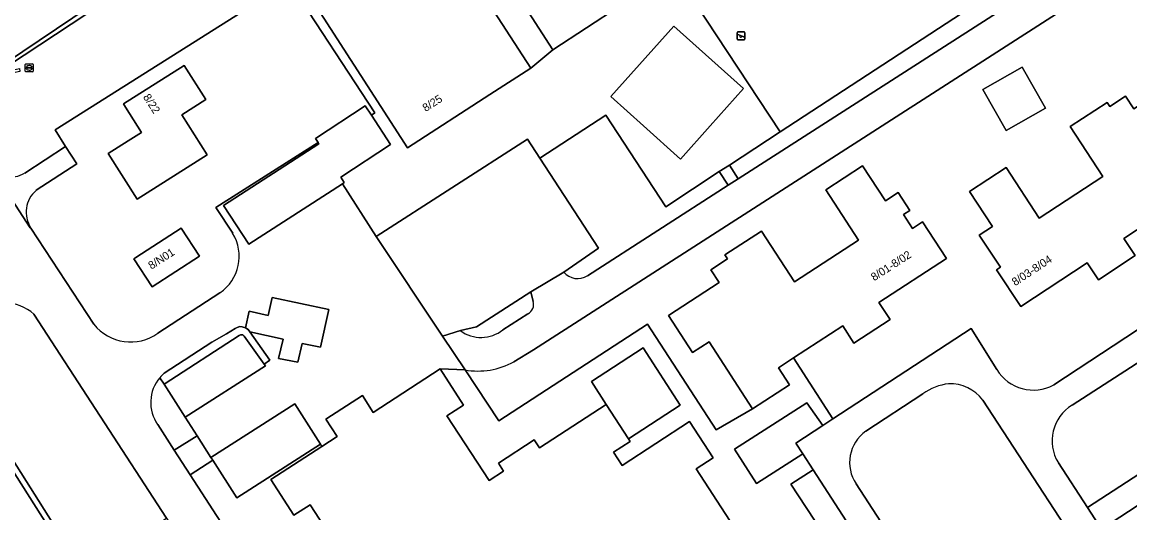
# Model space of a CAD drawing. Extents: x 159451 to 160664, y 388402 to 389723.
# Drawn here: x 159905.3 to 160043.7, y 389201.7 to 389263 of the extents above; entities that cross this region are included whole.
import ezdxf

# ---------------------------------------------------------------- set-up
doc = ezdxf.new("R2010")
doc.units = 0
for name, color, linetype in [('IMGEO_Erf', 7, 'Continuous'), ('IMGEO_Grasland_overig', 7, 'Continuous'), ('IMGEO_Groenvoorziening', 7, 'Continuous'), ('IMGEO_Haag', 7, 'Continuous'), ('IMGEO_Hek', 7, 'Continuous'), ('IMGEO_Meer_plas_ven_vijver', 7, 'Continuous'), ('IMGEO_Oever', 7, 'Continuous'), ('IMGEO_Open_loods', 7, 'Continuous'), ('IMGEO_Pand', 7, 'Continuous'), ('IMGEO_Pand_nummerreeks', 7, 'Continuous'), ('IMGEO_Parkeervlak_gesloten', 7, 'Continuous'), ('IMGEO_Parkeervlak_open', 7, 'Continuous'), ('IMGEO_Rijbaan_lokaal_gesloten', 7, 'Continuous'), ('IMGEO_Rijbaan_lokaal_open', 7, 'Continuous'), ('IMGEO_Rioolput', 7, 'Continuous'), ('IMGEO_Speelvoorziening', 7, 'Continuous'), ('IMGEO_Voetpad_gesloten', 7, 'Continuous'), ('IMGEO_Voetpad_open', 7, 'Continuous')]:
    doc.layers.add(name, color=color, linetype=linetype)

msp = doc.modelspace()

# ---------------------------------------------------------------- linework, layer by layer
at = {"layer": 'IMGEO_Erf'}
for points in [[(159942.27, 389247.93), (159941.93, 389248.42), (159948.15, 389252.52), (159948.93, 389251.33), (159949.38, 389251.62), (159938.65, 389268), (159909.42, 389249.5), (159910.72, 389247.44), (159912.11, 389245.25), (159907.06, 389241.97)], [(160041.99, 389268.82), (159969.19, 389222.03), (159966.74, 389220.55)], [(160034.2, 389217.64), (160072.99, 389243.15), (160062.76, 389252.92)], [(159931.6, 389236.59), (159929.51, 389239.79), (159942.27, 389247.93)], [(159960.64, 389219.52), (159964.87, 389213.17), (159983.45, 389225.22), (159992.01, 389212.02), (159996.56, 389214.67), (159991.13, 389223.04), (159989.07, 389221.71), (159986.07, 389226.32), (159992.41, 389230.43), (159991.37, 389232.03), (159993.45, 389233.38), (159993.11, 389233.9), (159997.69, 389236.87), (160001.8, 389230.53), (160009.8, 389235.72), (160005.72, 389242.01), (160010.32, 389244.99), (160013.16, 389240.62), (160014.77, 389241.66), (160016.22, 389239.43), (160015.44, 389238.93), (160016.56, 389237.2), (160017.81, 389238.01), (160020.79, 389233.42), (160012.36, 389227.95), (160013.75, 389225.81), (160009.22, 389222.88), (160007.84, 389225.01), (160001.7, 389221.03), (160006.59, 389213.4), (160023.88, 389224.68), (160027.09, 389219.58)], [(159906.39, 389237.24), (159914.25, 389225.23)], [(159922.25, 389224.11), (159930, 389229.16)], [(160071.89, 389220.37), (160040.16, 389199.62), (160049.04, 389185.76), (160029.31, 389172.93), (160027.27, 389171.6), (160021.26, 389180.85)]]:
    msp.add_lwpolyline(points, dxfattribs=at)
for points in [[(159928.4, 389246.38), (159919.68, 389240.85), (159916.06, 389246.57), (159918.55, 389248.15), (159920.2, 389249.19), (159918.21, 389252.32), (159917.95, 389252.74), (159925.55, 389257.56), (159928.24, 389253.3), (159925.23, 389251.39)], [(160028.25, 389249.43), (160025.34, 389254.56), (160030.26, 389257.35), (160033.17, 389252.23)], [(160051.44, 389250.36), (160056.92, 389242.01), (160052.29, 389238.96), (160050.87, 389241.12), (160042.98, 389235.94), (160044.38, 389233.81), (160039.78, 389230.79), (160038.4, 389232.89), (160030.09, 389227.43), (160027.07, 389232.03), (160027.53, 389232.34), (160024.89, 389236.34), (160026.55, 389237.42), (160023.67, 389241.8), (160028.24, 389244.79), (160032.39, 389238.47), (160040.35, 389243.69), (160036.26, 389249.91), (160040.87, 389252.94), (160041.2, 389252.44), (160043.16, 389253.73), (160044.21, 389252.13), (160050.55, 389256.29), (160053.54, 389251.73)], [(159927.45, 389233.73), (159921.54, 389229.88), (159919.25, 389233.38), (159919.52, 389233.55), (159925.17, 389237.24)]]:
    msp.add_lwpolyline(points, close=True, dxfattribs=at)
for centre, radius, start, end in [((159909.35, 389239.23), 3.56, 129.8908, 213.917), ((159926.93, 389233.71), 5.49, 303.9825, 31.7375), ((159918.84, 389228.86), 5.85, 218.3532, 305.7233), ((159962.24, 389228.59), 9.21, 259.9816, 299.2142), ((160031.66, 389222.34), 5.34, 211.2132, 298.3789)]:
    msp.add_arc(centre, radius, start, end, dxfattribs=at)
at = {"layer": 'IMGEO_Grasland_overig'}
msp.add_lwpolyline([(160001.98, 389210.39), (160005.34, 389212.58), (160003.34, 389215.4), (159994.33, 389209.63), (159997.08, 389205.34), (160002.85, 389209.04)], close=True, dxfattribs=at)
at = {"layer": 'IMGEO_Groenvoorziening'}
for points in [[(160006.58, 389324), (160004.92, 389322.82), (159998.09, 389318.4), (159982.41, 389309.54), (159903.59, 389257.53), (159904.23, 389257.01), (159904.97, 389257.18), (159905.01, 389256.78), (159904.21, 389256.61), (159903.51, 389257.12), (159903.1, 389257.75), (159896.07, 389253.11), (159898.08, 389250), (159901.3, 389245.03)], [(159995.54, 389307.61), (159964.99, 389287.63), (159973.59, 389274.49), (159977.01, 389276.73), (159979.17, 389273.42), (159980.94, 389274.58), (159987.74, 389264.19), (159989.42, 389265.29), (159986.18, 389270.18), (159974.59, 389287.89), (160008.08, 389309.69), (160019.69, 389292.19), (160033.58, 389271.21), (160000.03, 389249.27), (159993.67, 389245.11), (159994.77, 389243.39), (160043.54, 389274.71)], [(159905.61, 389244.11), (159910.72, 389247.44), (159909.42, 389249.5), (159938.65, 389268), (159939.64, 389268.65), (159954.42, 389278.21), (159953.27, 389279.96), (159964.99, 389287.63), (159995.54, 389307.61)], [(159978.23, 389251.35), (159969.99, 389245.96), (159977.33, 389234.74), (159973, 389231.74)], [(159975.92, 389231.28), (159993.51, 389242.58), (159992.41, 389244.29), (159985.72, 389239.91), (159978.23, 389251.35)], [(160077.34, 389226.4), (160076.35, 389240.87), (160068.36, 389235.7), (160036.5, 389215.12)], [(159969.16, 389228.08), (159968.86, 389229.29), (159962.06, 389224.9), (159960.05, 389224.43)], [(159917.7, 389197.36), (159923.34, 389201.02), (159906.77, 389226.48)], [(159965.37, 389224.54), (159968.5, 389226.54)], [(159933.73, 389224.28), (159933.54, 389224.59), (159933.21, 389224.77), (159932.8, 389224.9), (159932.48, 389224.94), (159932.16, 389224.82), (159931.93, 389224.69), (159930.82, 389224.04), (159929.01, 389222.99), (159923.06, 389219.11)], [(159922.5, 389218.55), (159923.02, 389217.75), (159932.41, 389223.83), (159932.49, 389223.86), (159932.59, 389223.89), (159932.66, 389223.91), (159932.8, 389223.92), (159932.88, 389223.89), (159932.96, 389223.83), (159933.04, 389223.75), (159935.55, 389220.26), (159936.23, 389220.72), (159933.73, 389224.28)], [(160034.78, 389207.9), (160038.43, 389202.32), (160059.58, 389216.09), (160069.88, 389222.95)], [(159890.55, 389218.64), (159894.92, 389221.41), (159895.56, 389221.81), (159910.27, 389198.6)], [(159895.56, 389221.81), (159894.92, 389221.41), (159909.11, 389199.03), (159909.62, 389198.21)], [(159910.27, 389198.6), (159895.56, 389221.81)], [(159925.67, 389213.61), (159923.02, 389217.75), (159922.5, 389218.55)], [(159922.23, 389212.7), (159924.29, 389209.5), (159927.16, 389211.29), (159925.67, 389213.61)], [(159945.81, 389191.21), (159947.88, 389192.55), (159941.29, 389202.68), (159939.26, 389201.36), (159936.36, 389205.82), (159942.76, 389209.97), (159942.59, 389210.24), (159932.13, 389203.53), (159929.12, 389208.23), (159926.29, 389206.42), (159942, 389182.2), (159947.2, 389185.57), (159959.65, 389166.36), (159954.45, 389162.99), (159957.06, 389158.96)], [(160013.39, 389192.75), (160004.14, 389207.04), (160001.35, 389205.26), (160008.23, 389194.81), (159996.97, 389187.41), (159993.6, 389192.53), (159982.65, 389185.33), (159987.56, 389177.52), (159991.19, 389171.98), (160000, 389177.64), (160011.84, 389185.26)]]:
    msp.add_lwpolyline(points, dxfattribs=at)
for points in [[(160019.69, 389292.19), (159986.18, 389270.18), (159989.42, 389265.29), (160000.03, 389249.27), (160033.58, 389271.21)], [(159955, 389278.59), (159968.84, 389257.2), (159971.62, 389259.5), (159968.55, 389264.2), (159957.78, 389280.5)], [(159978.29, 389215.21), (159981.08, 389210.9), (159987.54, 389215.1), (159982.88, 389222.28), (159976.42, 389218.09)]]:
    msp.add_lwpolyline(points, close=True, dxfattribs=at)
for centre, radius, start, end in [((159903.91, 389246.72), 3.11, 212.8795, 303.0689), ((159974.72, 389233.15), 2.22, 219.254, 302.7061), ((159902.79, 389221.88), 6.09, 49.1767, 123.8197), ((159967.93, 389227.69), 1.28, 296.3961, 17.2519), ((159962.64, 389227.95), 4.37, 233.6418, 308.6854), ((159926.08, 389215.55), 4.67, 130.4209, 140.0939), ((159926.19, 389215.44), 4.83, 139.8899, 214.6509), ((160039.25, 389210.65), 5.25, 121.5919, 211.583)]:
    msp.add_arc(centre, radius, start, end, dxfattribs=at)
at = {"layer": 'IMGEO_Haag'}
for points in [[(159895.56, 389221.81), (159894.92, 389221.41), (159909.11, 389199.03), (159909.62, 389198.21)], [(159910.27, 389198.6), (159895.56, 389221.81)]]:
    msp.add_lwpolyline(points, dxfattribs=at)
at = {"layer": 'IMGEO_Hek'}
for points in [[(160019.81, 389292.27), (160033.58, 389271.21), (160000.03, 389249.27)], [(160000.03, 389249.27), (159989.42, 389265.29)]]:
    msp.add_lwpolyline(points, dxfattribs=at)
at = {"layer": 'IMGEO_Meer_plas_ven_vijver'}
msp.add_lwpolyline([(159903.35, 389257.91), (159944.67, 389285.75), (160000, 389321.66), (160003.95, 389324.2), (160004.34, 389324.52), (160004.67, 389324.92), (160004.84, 389325.36), (160004.89, 389325.67), (160004.83, 389326.39), (160004.67, 389326.73), (160004.23, 389327.16), (160003.97, 389327.29), (160003.26, 389327.48), (160002.88, 389327.47), (160002.29, 389327.32), (160001.83, 389327.11), (160001.38, 389326.86), (159981.5, 389314.97), (159962.25, 389302.44), (159947.84, 389293.11), (159928.8, 389280.79), (159920.61, 389275.11), (159902.08, 389263.09)], dxfattribs=at)
at = {"layer": 'IMGEO_Oever'}
msp.add_lwpolyline([(160001.38, 389326.86), (160001.83, 389327.11), (160002.29, 389327.32), (160002.88, 389327.47), (160003.26, 389327.48), (160003.97, 389327.29), (160004.23, 389327.16), (160004.67, 389326.73), (160004.83, 389326.39), (160004.89, 389325.67), (160004.84, 389325.36), (160004.67, 389324.92), (160004.34, 389324.52), (160003.95, 389324.2), (160000, 389321.66), (159944.67, 389285.75), (159903.35, 389257.91), (159903.59, 389257.53), (159982.41, 389309.54), (159998.09, 389318.4), (160004.92, 389322.82), (160006.58, 389324), (160007.08, 389324.36)], dxfattribs=at)
at = {"layer": 'IMGEO_Open_loods'}
msp.add_lwpolyline([(159987.58, 389245.86), (159991.27, 389250), (159995.45, 389254.67), (159986.73, 389262.47), (159978.86, 389253.66), (159982.95, 389250)], close=True, dxfattribs=at)
at = {"layer": 'IMGEO_Pand'}
for points in [[(159954.42, 389278.21), (159939.64, 389268.65), (159953.46, 389247.26), (159963.74, 389253.9), (159968.84, 389257.2), (159955, 389278.59)], [(159976.93, 389269.69), (159968.55, 389264.2), (159971.62, 389259.5), (159980.01, 389264.98)], [(159925.23, 389251.39), (159928.24, 389253.3), (159925.55, 389257.56), (159917.95, 389252.74), (159918.21, 389252.32), (159920.2, 389249.19), (159918.55, 389248.15), (159916.06, 389246.57), (159919.68, 389240.85), (159928.4, 389246.38)], [(160030.26, 389257.35), (160025.34, 389254.56), (160028.25, 389249.43), (160033.17, 389252.23)], [(160030.09, 389227.43), (160038.4, 389232.89), (160039.78, 389230.79), (160044.38, 389233.81), (160042.98, 389235.94), (160050.87, 389241.12), (160052.29, 389238.96), (160056.92, 389242.01), (160051.44, 389250.36), (160053.54, 389251.73), (160050.55, 389256.29), (160044.21, 389252.13), (160043.16, 389253.73), (160041.2, 389252.44), (160040.87, 389252.94), (160036.26, 389249.91), (160040.35, 389243.69), (160032.39, 389238.47), (160028.24, 389244.79), (160023.67, 389241.8), (160026.55, 389237.42), (160024.89, 389236.34), (160027.53, 389232.34), (160027.07, 389232.03)], [(159948.15, 389252.52), (159941.93, 389248.42), (159942.27, 389247.93), (159942.38, 389247.76), (159930.47, 389240.07), (159933.62, 389235.21), (159945.31, 389242.77), (159945.54, 389242.92), (159945.11, 389243.59), (159951.31, 389247.67), (159948.93, 389251.33)], [(159996.56, 389214.67), (160001.19, 389217.67), (159999.81, 389219.8), (160001.7, 389221.03), (160007.84, 389225.01), (160009.22, 389222.88), (160013.75, 389225.81), (160012.36, 389227.95), (160020.79, 389233.42), (160017.81, 389238.01), (160016.56, 389237.2), (160015.44, 389238.93), (160016.22, 389239.43), (160014.77, 389241.66), (160013.16, 389240.62), (160010.32, 389244.99), (160005.72, 389242.01), (160009.8, 389235.72), (160001.8, 389230.53), (159997.69, 389236.87), (159993.11, 389233.9), (159993.45, 389233.38), (159991.37, 389232.03), (159992.41, 389230.43), (159986.07, 389226.32), (159989.07, 389221.71), (159991.13, 389223.04)], [(159919.25, 389233.38), (159921.54, 389229.88), (159927.45, 389233.73), (159925.17, 389237.24), (159919.52, 389233.55)]]:
    msp.add_lwpolyline(points, close=True, dxfattribs=at)
msp.add_lwpolyline([(159996.29, 389196.72), (159989.51, 389207.16), (159991.63, 389208.54), (159988.7, 389213.06), (159980.27, 389207.59), (159979.19, 389209.25), (159981.27, 389210.6), (159981.08, 389210.9), (159978.29, 389215.21), (159969.94, 389209.79), (159969.29, 389210.79), (159964.8, 389207.88), (159965.46, 389206.86), (159963.64, 389205.69), (159958.38, 389213.79), (159960.45, 389215.13), (159957.53, 389219.64), (159949.17, 389214.22), (159947.82, 389216.31), (159943.26, 389213.35), (159944.65, 389211.2), (159942.76, 389209.97), (159936.36, 389205.82), (159939.26, 389201.36), (159941.29, 389202.68), (159947.88, 389192.55)], dxfattribs=at)
at = {"layer": 'IMGEO_Parkeervlak_gesloten'}
msp.add_lwpolyline([(159935.71, 389220.04), (159935.55, 389220.26), (159933.04, 389223.75), (159932.96, 389223.83), (159932.88, 389223.89), (159932.8, 389223.92), (159932.66, 389223.91), (159932.59, 389223.89), (159932.49, 389223.86), (159932.41, 389223.83), (159923.02, 389217.75), (159925.67, 389213.61)], close=True, dxfattribs=at)
msp.add_lwpolyline([(159909.62, 389198.21), (159909.11, 389199.03), (159894.92, 389221.41)], dxfattribs=at)
at = {"layer": 'IMGEO_Parkeervlak_open'}
for points in [[(159977.33, 389234.74), (159969.99, 389245.96), (159968.45, 389248.36), (159949.55, 389236.19), (159957.82, 389223.75), (159960.05, 389224.43), (159962.06, 389224.9), (159968.86, 389229.29), (159973, 389231.74)], [(159936.04, 389226.3), (159933.66, 389226.85), (159933.21, 389224.77), (159933.54, 389224.59), (159933.73, 389224.28), (159937.9, 389223.38), (159937.34, 389220.96), (159939.76, 389220.51), (159940.3, 389222.84), (159942.58, 389222.36), (159943.6, 389227.05), (159936.52, 389228.55)], [(159942.59, 389210.24), (159939.35, 389215.29), (159928.89, 389208.58), (159929.12, 389208.23), (159932.13, 389203.53)]]:
    msp.add_lwpolyline(points, close=True, dxfattribs=at)
at = {"layer": 'IMGEO_Rijbaan_lokaal_gesloten'}
for points in [[(160050.65, 389266.93), (160062.76, 389252.92), (160072.99, 389243.15), (160076.29, 389245.32), (160075, 389246.59), (160063.52, 389257.98), (160054.86, 389268.6), (160052.78, 389272.29), (160050.84, 389276.24), (160049.4, 389278.45), (160043.54, 389274.71), (159994.77, 389243.39), (159993.51, 389242.58), (159975.92, 389231.28)], [(159966.74, 389220.55), (159969.19, 389222.03), (160041.99, 389268.82)], [(159973, 389231.74), (159968.86, 389229.29), (159969.16, 389228.08)], [(159968.5, 389226.54), (159965.37, 389224.54)], [(159960.05, 389224.43), (159957.82, 389223.75), (159960.64, 389219.52)]]:
    msp.add_lwpolyline(points, dxfattribs=at)
for centre, radius, start, end in [((159974.72, 389233.15), 2.22, 219.254, 302.7061), ((159967.93, 389227.69), 1.28, 296.3961, 17.2519), ((159962.64, 389227.95), 4.37, 233.6418, 308.6854), ((159962.24, 389228.59), 9.21, 259.9816, 299.2142)]:
    msp.add_arc(centre, radius, start, end, dxfattribs=at)
at = {"layer": 'IMGEO_Rijbaan_lokaal_open'}
for points in [[(159914.25, 389225.23), (159906.39, 389237.24), (159906.29, 389237.28), (159901.29, 389244.93), (159901.3, 389245.03), (159898.08, 389250), (159896.07, 389253.11), (159891.58, 389250.15), (159891.68, 389250), (159898.68, 389238.98)], [(159912.11, 389245.25), (159910.72, 389247.44), (159905.61, 389244.11)], [(159923.06, 389219.11), (159929.01, 389222.99), (159930.82, 389224.04), (159931.93, 389224.69), (159932.16, 389224.82), (159932.48, 389224.94), (159932.8, 389224.9), (159933.21, 389224.77), (159933.66, 389226.85), (159936.04, 389226.3), (159936.52, 389228.55), (159943.6, 389227.05), (159942.58, 389222.36), (159940.3, 389222.84), (159939.76, 389220.51), (159937.34, 389220.96), (159937.9, 389223.38), (159933.73, 389224.28), (159936.23, 389220.72), (159935.55, 389220.26), (159935.71, 389220.04), (159925.67, 389213.61), (159927.16, 389211.29), (159928.89, 389208.58), (159939.35, 389215.29), (159942.59, 389210.24), (159942.76, 389209.97), (159944.65, 389211.2), (159943.26, 389213.35), (159947.82, 389216.31), (159949.17, 389214.22), (159957.53, 389219.64), (159960.64, 389219.52), (159957.82, 389223.75), (159949.55, 389236.19), (159945.31, 389242.77), (159933.62, 389235.21), (159930.47, 389240.07), (159942.38, 389247.76), (159942.27, 389247.93), (159929.51, 389239.79), (159931.6, 389236.59)], [(160075, 389246.59), (160076.29, 389245.32), (160072.99, 389243.15), (160034.2, 389217.64)], [(159901.3, 389245.03), (159901.29, 389244.93), (159906.29, 389237.28), (159906.39, 389237.24)], [(159907.06, 389241.97), (159912.11, 389245.25)], [(160036.5, 389215.12), (160068.36, 389235.7), (160076.35, 389240.87), (160077.54, 389241.64)], [(159930, 389229.16), (159922.25, 389224.11)], [(159906.77, 389226.48), (159923.34, 389201.02), (159923.61, 389200.6), (159924.57, 389199.14), (159937.57, 389179.15), (159937.96, 389178.56), (159949.41, 389160.96), (159949.79, 389160.37), (159952.53, 389156.15)], [(160027.09, 389219.58), (160023.88, 389224.68), (160006.59, 389213.4), (160005.34, 389212.58), (160001.98, 389210.39), (160002.85, 389209.04), (160004.14, 389207.04), (160013.39, 389192.75)], [(160010.74, 389211.86), (160017.84, 389216.54)], [(160025.35, 389215.76), (160041.22, 389191.43)], [(159957.06, 389158.96), (159954.45, 389162.99), (159954.07, 389163.57), (159942.38, 389181.61), (159942, 389182.2), (159926.29, 389206.42), (159924.29, 389209.5), (159922.23, 389212.7)], [(160021.26, 389180.85), (160027.27, 389171.6), (160029.31, 389172.93), (160049.04, 389185.76), (160040.16, 389199.62), (160038.43, 389202.32), (160034.78, 389207.9)], [(160025.38, 389180.86), (160009.52, 389205.29)]]:
    msp.add_lwpolyline(points, dxfattribs=at)
msp.add_lwpolyline([(159927.16, 389211.29), (159924.29, 389209.5), (159926.29, 389206.42), (159929.12, 389208.23), (159928.89, 389208.58)], close=True, dxfattribs=at)
for centre, radius, start, end in [((159903.91, 389246.72), 3.11, 212.8795, 303.0689), ((159909.35, 389239.23), 3.56, 129.8908, 213.917), ((159926.93, 389233.71), 5.49, 303.9825, 31.7375), ((159902.79, 389221.88), 6.09, 49.1767, 123.8197), ((159918.84, 389228.86), 5.85, 218.3532, 305.7233), ((159926.08, 389215.55), 4.67, 130.4209, 140.0939), ((160031.66, 389222.34), 5.34, 211.2132, 298.3789), ((159926.19, 389215.44), 4.83, 139.8899, 214.6509), ((160021.89, 389210.9), 6.94, 96.7893, 125.6448), ((160021.25, 389212.66), 5.13, 37.0681, 92.0302), ((160039.25, 389210.65), 5.25, 121.5919, 211.583), ((160013.43, 389207.96), 4.74, 124.6581, 214.4027)]:
    msp.add_arc(centre, radius, start, end, dxfattribs=at)
at = {"layer": 'IMGEO_Rioolput'}
for p, q in [((159905.68, 389256.82), (159905.68, 389257.68)), ((159905.75, 389257.75), (159906.6, 389257.75)), ((159906.6, 389256.75), (159905.75, 389256.75)), ((159905.94, 389257.24), (159905.94, 389257.26)), ((159905.98, 389257.29), (159906.38, 389257.29)), ((159906.37, 389257.21), (159905.98, 389257.21)), ((159906.19, 389256.97), (159906.16, 389256.97)), ((159906.17, 389257.53), (159906.19, 389257.53)), ((159906.42, 389257.26), (159906.42, 389257.24)), ((159906.68, 389257.68), (159906.68, 389256.82))]:
    msp.add_line(p, q, dxfattribs=at)
for points in [[(159905.68, 389256.82), (159905.68, 389257.68)], [(159905.75, 389257.75), (159906.6, 389257.75)], [(159906.6, 389256.75), (159905.75, 389256.75)], [(159906.68, 389257.68), (159906.68, 389256.82)]]:
    msp.add_lwpolyline(points, dxfattribs=at)
for centre, radius, start, end in [((159905.75, 389257.67), 0.0765, 91.552, 178.448), ((159905.75, 389257.67), 0.0765, 91.552, 178.448), ((159905.75, 389256.83), 0.0765, 181.552, 268.448), ((159905.75, 389256.83), 0.0765, 181.552, 268.448), ((159905.98, 389257.25), 0.0403, 85.8775, 175.7526), ((159905.97, 389257.24), 0.0366, 178.938, 274.7102), ((159906.38, 389257.25), 0.043, 264.8664, 352.4533), ((159906.38, 389257.25), 0.0386, 1.7309, 96.639), ((159906.6, 389257.67), 0.0765, 1.552, 88.448), ((159906.6, 389257.67), 0.0765, 1.552, 88.448), ((159906.6, 389256.83), 0.0765, 271.552, 358.448), ((159906.6, 389256.83), 0.0765, 271.552, 358.448)]:
    msp.add_arc(centre, radius, start, end, dxfattribs=at)
for centre, major_axis, ratio, start_param, end_param in [((159906.16, 389257.25), (-0.387, 0.002), 0.722429, 4.712389, 7.853982), ((159906.19, 389257.25), (-0.39, 0.002), 0.717154, 1.570796, 4.712389)]:
    msp.add_ellipse(centre, major_axis=major_axis, ratio=ratio, start_param=start_param, end_param=end_param, dxfattribs=at)
at = {"layer": 'IMGEO_Speelvoorziening'}
for p, q in [((159994.63, 389260.84), (159994.63, 389261.64)), ((159994.63, 389261.64), (159994.63, 389260.84)), ((159995.01, 389261.27), (159994.68, 389261.41)), ((159994.7, 389261.47), (159995.58, 389261.12)), ((159994.73, 389261.74), (159995.52, 389261.74)), ((159995.52, 389261.74), (159994.73, 389261.74)), ((159995.52, 389260.74), (159994.73, 389260.74)), ((159994.73, 389260.74), (159995.52, 389260.74)), ((159995.55, 389261.05), (159995.21, 389261.19)), ((159995.62, 389261.64), (159995.62, 389260.84)), ((159995.62, 389260.84), (159995.62, 389261.64))]:
    msp.add_line(p, q, dxfattribs=at)
for centre, radius, start, end in [((159994.73, 389261.64), 0.1, 90, 180), ((159994.73, 389261.64), 0.1, 90, 180), ((159994.73, 389260.84), 0.1, 180, 270), ((159994.73, 389260.84), 0.1, 180, 270), ((159994.69, 389261.44), 0.0327, 68.078, 248.078), ((159995.09, 389261.18), 0.12, 130.9928, 5.1632), ((159995.52, 389261.64), 0.1, 0, 90), ((159995.52, 389261.64), 0.1, 360, 90), ((159995.52, 389260.84), 0.1, 270, 0), ((159995.52, 389260.84), 0.1, 270, 0), ((159995.56, 389261.09), 0.0327, 248.078, 68.078)]:
    msp.add_arc(centre, radius, start, end, dxfattribs=at)
at = {"layer": 'IMGEO_Voetpad_gesloten'}
for points in [[(160069.88, 389222.95), (160059.58, 389216.09), (160038.43, 389202.32), (160040.16, 389199.62), (160071.89, 389220.37)], [(160017.84, 389216.54), (160010.74, 389211.86)], [(160041.22, 389191.43), (160025.35, 389215.76)], [(160009.52, 389205.29), (160025.38, 389180.86)]]:
    msp.add_lwpolyline(points, dxfattribs=at)
for centre, radius, start, end in [((160021.89, 389210.9), 6.94, 96.7893, 125.6448), ((160021.25, 389212.66), 5.13, 37.0681, 92.0302), ((160013.43, 389207.96), 4.74, 124.6581, 214.4027)]:
    msp.add_arc(centre, radius, start, end, dxfattribs=at)
at = {"layer": 'IMGEO_Voetpad_open'}
for points in [[(159938.65, 389268), (159949.38, 389251.62), (159948.93, 389251.33), (159951.31, 389247.67), (159945.11, 389243.59), (159945.54, 389242.92), (159945.31, 389242.77), (159949.55, 389236.19), (159968.45, 389248.36), (159969.99, 389245.96), (159978.23, 389251.35), (159985.72, 389239.91), (159992.41, 389244.29), (159993.67, 389245.11), (160000.03, 389249.27), (159989.42, 389265.29)], [(159980.01, 389264.98), (159971.62, 389259.5), (159968.84, 389257.2), (159963.74, 389253.9), (159953.46, 389247.26), (159939.64, 389268.65)], [(160008.23, 389194.81), (160001.35, 389205.26), (160004.14, 389207.04), (160002.85, 389209.04), (159997.08, 389205.34), (159994.33, 389209.63), (160003.34, 389215.4), (160005.34, 389212.58), (160006.59, 389213.4), (160001.7, 389221.03), (159999.81, 389219.8), (160001.19, 389217.67), (159996.56, 389214.67), (159992.01, 389212.02), (159983.45, 389225.22), (159964.87, 389213.17), (159960.64, 389219.52), (159957.53, 389219.64), (159960.45, 389215.13), (159958.38, 389213.79), (159963.64, 389205.69), (159965.46, 389206.86), (159964.8, 389207.88), (159969.29, 389210.79), (159969.94, 389209.79), (159978.29, 389215.21), (159976.42, 389218.09), (159982.88, 389222.28), (159987.54, 389215.1), (159981.08, 389210.9), (159981.27, 389210.6), (159979.19, 389209.25), (159980.27, 389207.59), (159988.7, 389213.06), (159991.63, 389208.54), (159989.51, 389207.16), (159996.29, 389196.72)]]:
    msp.add_lwpolyline(points, dxfattribs=at)
for points in [[(159986.73, 389262.47), (159995.45, 389254.67), (159991.27, 389250), (159987.58, 389245.86), (159982.95, 389250), (159978.86, 389253.66)], [(159993.67, 389245.11), (159992.41, 389244.29), (159993.51, 389242.58), (159994.77, 389243.39)]]:
    msp.add_lwpolyline(points, close=True, dxfattribs=at)

# ---------------------------------------------------------------- texts
at = {"layer": 'IMGEO_Pand_nummerreeks'}
for s, rotation, p in [('8/22', 302.5209, (159920.36, 389253.61)), ('8/25', 32.7357, (159955.72, 389251.72)), ('8/N01', 32.8385, (159921.45, 389232.03)), ('8/01-8/02', 32.8773, (160011.76, 389230.58)), ('8/03-8/04', 33.4838, (160029.38, 389229.97))]:
    msp.add_text(s, height=1, rotation=rotation, dxfattribs=at).set_placement(p)

doc.saveas('drawing.dxf')
